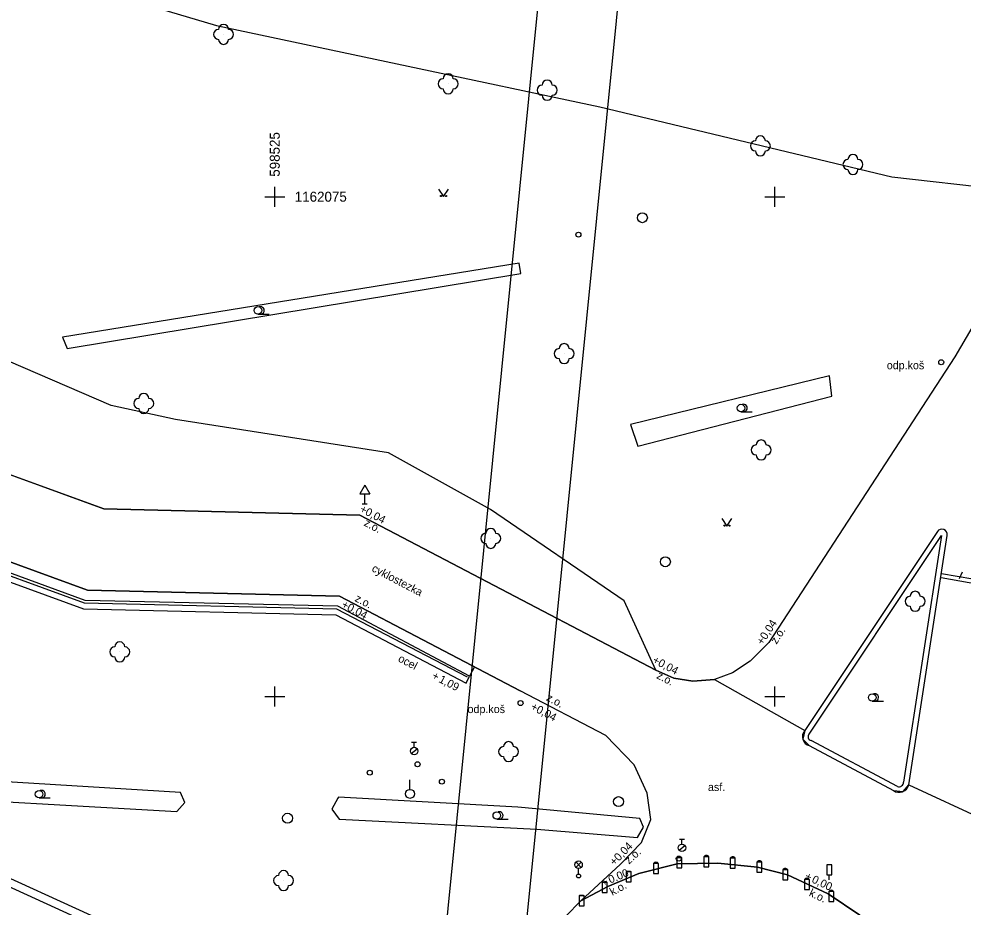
# Model space of a CAD drawing. Extents: x -598693 to -598360, y -1162453 to -1162007.
# Drawn here: x -598537.79 to -598490.58, y -1162110.54 to -1162066.1 of the extents above; entities that cross this region are included whole.
import ezdxf

# ---------------------------------------------------------------- set-up
doc = ezdxf.new("R2010")
doc.units = 0
for name, color, linetype in [('Vrstva 11', 7, 'Continuous'), ('Vrstva 14', 7, 'Continuous'), ('Vrstva 15', 7, 'Continuous'), ('Vrstva 17', 7, 'Continuous'), ('Vrstva 19', 7, 'Continuous'), ('Vrstva 2', 7, 'Continuous'), ('Vrstva 22', 7, 'Continuous'), ('Vrstva 24', 7, 'Continuous'), ('Vrstva 25', 7, 'Continuous'), ('Vrstva 29', 7, 'Continuous'), ('Vrstva 4', 7, 'Continuous'), ('Vrstva 41', 7, 'Continuous'), ('Vrstva 44', 7, 'Continuous'), ('Vrstva 49', 7, 'Continuous'), ('Vrstva 50', 7, 'Continuous'), ('Vrstva 62', 7, 'Continuous'), ('Vrstva 63', 7, 'Continuous'), ('Vrstva 7', 7, 'Continuous')]:
    doc.layers.add(name, color=color, linetype=linetype)

msp = doc.modelspace()

# ---------------------------------------------------------------- linework, layer by layer
at = {"layer": 'Vrstva 11'}
for points in [[(-598535.61, -1162082.02), (-598535.38, -1162082.6), (-598512.7, -1162078.84), (-598512.78, -1162078.32)], [(-598512.78, -1162078.32), (-598535.61, -1162082.02)], [(-598497.14, -1162084.97), (-598497.27, -1162083.96), (-598507.22, -1162086.4), (-598506.85, -1162087.48)], [(-598506.85, -1162087.48), (-598497.14, -1162084.97)], [(-598529.9, -1162105.76), (-598529.5, -1162105.3), (-598529.72, -1162104.81), (-598544.4, -1162103.91), (-598544.73, -1162104.43), (-598544.52, -1162104.92)], [(-598544.52, -1162104.92), (-598529.9, -1162105.76)], [(-598511.89, -1162106.63), (-598506.87, -1162107.06), (-598506.57, -1162106.54), (-598506.75, -1162106.1), (-598512.85, -1162105.53), (-598521.81, -1162105.04), (-598521.84, -1162105.08), (-598522.15, -1162105.64), (-598521.78, -1162106.14)], [(-598521.78, -1162106.14), (-598511.89, -1162106.63)]]:
    msp.add_lwpolyline(points, dxfattribs=at)
at = {"layer": 'Vrstva 14'}
for p, q in [((-598525.84, -1162080.876), (-598525.278, -1162080.876)), ((-598501.689, -1162085.759), (-598501.126, -1162085.759)), ((-598495.126, -1162100.239), (-598494.563, -1162100.239)), ((-598536.784, -1162105.076), (-598536.222, -1162105.076)), ((-598513.899, -1162106.142), (-598513.337, -1162106.142))]:
    msp.add_line(p, q, dxfattribs=at)
for points in [[(-598516.812, -1162074.615), (-598516.562, -1162074.99), (-598516.312, -1162074.615)], [(-598502.64, -1162091.105), (-598502.39, -1162091.48), (-598502.14, -1162091.105)]]:
    msp.add_lwpolyline(points, dxfattribs=at)
for centre, radius in [((-598527.56, -1162066.88), 0.00025), ((-598516.33, -1162069.35), 0.00025), ((-598511.38, -1162069.67), 0.00025), ((-598500.72, -1162072.46), 0.00025), ((-598496.09, -1162073.39), 0.00025), ((-598516.687, -1162074.965), 0.025), ((-598516.437, -1162074.965), 0.025), ((-598525.84, -1162080.688), 0.188), ((-598510.53, -1162082.85), 0.00025), ((-598531.55, -1162085.34), 0.00025), ((-598501.689, -1162085.571), 0.188), ((-598500.68, -1162087.67), 0.00025), ((-598502.515, -1162091.455), 0.025), ((-598502.265, -1162091.455), 0.025), ((-598514.2, -1162092.09), 0.00025), ((-598492.98, -1162095.24), 0.00025), ((-598532.75, -1162097.77), 0.00025), ((-598495.126, -1162100.051), 0.188), ((-598513.31, -1162102.76), 0.00025), ((-598536.784, -1162104.888), 0.188), ((-598513.899, -1162105.954), 0.188), ((-598524.56, -1162109.21), 0.00025)]:
    msp.add_circle(centre, radius, dxfattribs=at)
for centre, radius, start, end in [((-598527.56, -1162066.63), 0.25, 0, 180), ((-598527.81, -1162066.88), 0.25, 90, 270), ((-598527.31, -1162066.88), 0.25, 270, 90), ((-598527.56, -1162067.13), 0.25, 180, 360), ((-598516.33, -1162069.1), 0.25, 0, 180), ((-598516.58, -1162069.35), 0.25, 90, 270), ((-598516.08, -1162069.35), 0.25, 270, 90), ((-598511.38, -1162069.42), 0.25, 0, 180), ((-598516.33, -1162069.6), 0.25, 180, 360), ((-598511.63, -1162069.67), 0.25, 90, 270), ((-598511.13, -1162069.67), 0.25, 270, 90), ((-598511.38, -1162069.92), 0.25, 180, 360), ((-598500.97, -1162072.46), 0.25, 90, 270), ((-598500.72, -1162072.21), 0.25, 0, 180), ((-598500.47, -1162072.46), 0.25, 270, 90), ((-598500.72, -1162072.71), 0.25, 180, 360), ((-598496.34, -1162073.39), 0.25, 90, 270), ((-598496.09, -1162073.14), 0.25, 0, 180), ((-598495.84, -1162073.39), 0.25, 270, 90), ((-598496.09, -1162073.64), 0.25, 180, 360), ((-598525.715, -1162080.688), 0.188, 249.4944, 109.0474), ((-598510.53, -1162082.6), 0.25, 0, 180), ((-598510.78, -1162082.85), 0.25, 90, 270), ((-598510.28, -1162082.85), 0.25, 270, 90), ((-598510.53, -1162083.1), 0.25, 180, 360), ((-598531.55, -1162085.09), 0.25, 0, 180), ((-598531.8, -1162085.34), 0.25, 90, 270), ((-598531.3, -1162085.34), 0.25, 270, 90), ((-598501.564, -1162085.571), 0.188, 249.4944, 109.0474), ((-598531.55, -1162085.59), 0.25, 180, 360), ((-598500.68, -1162087.42), 0.25, 0, 180), ((-598500.93, -1162087.67), 0.25, 90, 270), ((-598500.43, -1162087.67), 0.25, 270, 90), ((-598500.68, -1162087.92), 0.25, 180, 360), ((-598514.45, -1162092.09), 0.25, 90, 270), ((-598514.2, -1162091.84), 0.25, 0, 180), ((-598513.95, -1162092.09), 0.25, 270, 90), ((-598514.2, -1162092.34), 0.25, 180, 360), ((-598492.98, -1162094.99), 0.25, 0, 180), ((-598493.23, -1162095.24), 0.25, 90, 270), ((-598492.73, -1162095.24), 0.25, 270, 90), ((-598492.98, -1162095.49), 0.25, 180, 360), ((-598533, -1162097.77), 0.25, 90, 270), ((-598532.75, -1162097.52), 0.25, 0, 180), ((-598532.5, -1162097.77), 0.25, 270, 90), ((-598532.75, -1162098.02), 0.25, 180, 360), ((-598495.001, -1162100.051), 0.188, 249.4944, 109.0474), ((-598513.31, -1162102.51), 0.25, 0, 180), ((-598513.56, -1162102.76), 0.25, 90, 270), ((-598513.06, -1162102.76), 0.25, 270, 90), ((-598513.31, -1162103.01), 0.25, 180, 360), ((-598536.659, -1162104.888), 0.188, 249.4944, 109.0474), ((-598513.774, -1162105.954), 0.188, 249.4944, 109.0474), ((-598524.81, -1162109.21), 0.25, 90, 270), ((-598524.56, -1162108.96), 0.25, 0, 180), ((-598524.31, -1162109.21), 0.25, 270, 90), ((-598524.56, -1162109.46), 0.25, 180, 360)]:
    msp.add_arc(centre, radius, start, end, dxfattribs=at)
at = {"layer": 'Vrstva 15'}
msp.add_line((-598497.28, -1162109.17), (-598497.28, -1162108.92), dxfattribs=at)
msp.add_lwpolyline([(-598497.405, -1162108.92), (-598497.155, -1162108.92), (-598497.155, -1162108.42), (-598497.405, -1162108.42)], close=True, dxfattribs=at)
for centre, radius in [((-598491.68, -1162083.28), 0.125), ((-598491.68, -1162083.28), 0.00025), ((-598512.71, -1162100.33), 0.125), ((-598512.71, -1162100.33), 0.00025)]:
    msp.add_circle(centre, radius, dxfattribs=at)
at = {"layer": 'Vrstva 17'}
for p, q in [((-598491.87, -1162091.75), (-598498.5, -1162101.71)), ((-598498.28, -1162101.885), (-598491.664, -1162091.946))]:
    msp.add_line(p, q, dxfattribs=at)
for points in [[(-598562.469, -1162084.303), (-598562.81, -1162085.24), (-598547.62, -1162090.84), (-598534.57, -1162095.61), (-598521.94, -1162095.91), (-598515.43, -1162099.34), (-598515.26, -1162098.99)], [(-598521.85, -1162095.48), (-598534.48, -1162095.2), (-598562.21, -1162085.02), (-598562.04, -1162084.57), (-598562.01, -1162084.47)], [(-598491.664, -1162091.946), (-598493.563, -1162104.286)], [(-598493.3, -1162104.42), (-598491.38, -1162091.94)], [(-598515.26, -1162098.99), (-598521.85, -1162095.48)], [(-598493.865, -1162104.502), (-598498.182, -1162102.195)], [(-598498.28, -1162102.46), (-598494.07, -1162104.71)]]:
    msp.add_lwpolyline(points, dxfattribs=at)
for centre, radius, start, end in [((-598491.648, -1162091.903), 0.27, 352.1581, 145.4538), ((-598498.157, -1162102.017), 0.46, 138.2563, 254.4401), ((-598498.157, -1162102.017), 0.18, 133.4026, 262.0107), ((-598493.789, -1162104.289), 0.226, 250.2488, 0.6288), ((-598493.789, -1162104.289), 0.506, 236.2848, 344.9903)]:
    msp.add_arc(centre, radius, start, end, dxfattribs=at)
at = {"layer": 'Vrstva 19'}
for p, q in [((-598520.5, -1162089.437), (-598520.75, -1162089.87)), ((-598520.5, -1162089.437), (-598520.25, -1162089.87)), ((-598520.75, -1162089.87), (-598520.25, -1162089.87)), ((-598520.5, -1162090.37), (-598520.5, -1162089.87)), ((-598520.625, -1162090.37), (-598520.375, -1162090.37))]:
    msp.add_line(p, q, dxfattribs=at)
at = {"layer": 'Vrstva 2'}
for points in [[(-598692.873, -1162424.561), (-598651.24, -1162006.63), (-598503.471, -1162021.35), (-598545.104, -1162439.282)], [(-598692.873, -1162424.561), (-598651.24, -1162006.63), (-598503.471, -1162021.35), (-598545.104, -1162439.282)], [(-598507.399, -1162020.712), (-598549.031, -1162438.644), (-598401.263, -1162453.364), (-598359.63, -1162035.432)]]:
    msp.add_lwpolyline(points, close=True, dxfattribs=at)
at = {"layer": 'Vrstva 22'}
msp.add_lwpolyline([(-598515.36, -1162099.04), (-598521.9, -1162095.63), (-598534.52, -1162095.33), (-598547.5, -1162090.6), (-598562.42, -1162085.09), (-598557.86, -1162072.77)], dxfattribs=at)
at = {"layer": 'Vrstva 24'}
for p, q in [((-598518.155, -1162102.292), (-598517.905, -1162102.292)), ((-598518.03, -1162102.542), (-598518.03, -1162102.292)), ((-598518.177, -1162102.846), (-598517.882, -1162102.614)), ((-598504.765, -1162107.132), (-598504.515, -1162107.132)), ((-598504.64, -1162107.382), (-598504.64, -1162107.132)), ((-598504.787, -1162107.686), (-598504.492, -1162107.454))]:
    msp.add_line(p, q, dxfattribs=at)
for centre, radius in [((-598509.82, -1162076.9), 0.125), ((-598518.03, -1162102.73), 0.188), ((-598517.86, -1162103.39), 0.125), ((-598520.25, -1162103.81), 0.125), ((-598516.64, -1162104.26), 0.125), ((-598504.64, -1162107.57), 0.188), ((-598504.8, -1162108.11), 0.125)]:
    msp.add_circle(centre, radius, dxfattribs=at)
at = {"layer": 'Vrstva 25'}
for points in [[(-598491.66, -1162093.84), (-598487.75, -1162094.52)], [(-598491.68, -1162094.05), (-598487.77, -1162094.75)]]:
    msp.add_lwpolyline(points, dxfattribs=at)
for centre in [(-598506.62, -1162076.05), (-598505.47, -1162093.26), (-598507.81, -1162105.26), (-598524.36, -1162106.09)]:
    msp.add_circle(centre, 0.25, dxfattribs=at)
at = {"layer": 'Vrstva 29'}
for p, q in [((-598509.942, -1162108.549), (-598509.678, -1162108.285)), ((-598509.674, -1162108.548), (-598509.938, -1162108.283)), ((-598509.81, -1162108.88), (-598509.81, -1162108.605))]:
    msp.add_line(p, q, dxfattribs=at)
for centre, radius in [((-598509.81, -1162108.417), 0.188), ((-598509.81, -1162108.98), 0.1)]:
    msp.add_circle(centre, radius, dxfattribs=at)
at = {"layer": 'Vrstva 4'}
msp.add_lwpolyline([(-598549.81, -1162104.23), (-598524.16, -1162115.97)], dxfattribs=at)
at = {"layer": 'Vrstva 41'}
for points in [[(-598555.19, -1162057.68), (-598541.03, -1162062.54), (-598527.91, -1162066.44), (-598508.75, -1162070.51), (-598494.14, -1162074), (-598488.83, -1162074.61)], [(-598505.95, -1162098.69), (-598507.53, -1162095.22), (-598514.22, -1162090.64), (-598519.32, -1162087.82), (-598529.96, -1162086.14), (-598533.18, -1162085.44), (-598556.77, -1162075.25)]]:
    msp.add_lwpolyline(points, dxfattribs=at)
at = {"layer": 'Vrstva 44'}
msp.add_line((-598518.24, -1162104.645), (-598518.24, -1162104.174), dxfattribs=at)
for points in [[(-598504.905, -1162108.57), (-598504.655, -1162108.57), (-598504.655, -1162108.07), (-598504.905, -1162108.07)], [(-598503.545, -1162108.52), (-598503.295, -1162108.52), (-598503.295, -1162108.02), (-598503.545, -1162108.02)], [(-598502.225, -1162108.58), (-598501.975, -1162108.58), (-598501.975, -1162108.08), (-598502.225, -1162108.08)], [(-598506.065, -1162108.86), (-598505.815, -1162108.86), (-598505.815, -1162108.36), (-598506.065, -1162108.36)], [(-598500.895, -1162108.79), (-598500.645, -1162108.79), (-598500.645, -1162108.29), (-598500.895, -1162108.29)], [(-598507.435, -1162109.27), (-598507.185, -1162109.27), (-598507.185, -1162108.77), (-598507.435, -1162108.77)], [(-598499.605, -1162109.17), (-598499.355, -1162109.17), (-598499.355, -1162108.67), (-598499.605, -1162108.67)], [(-598508.635, -1162109.81), (-598508.385, -1162109.81), (-598508.385, -1162109.31), (-598508.635, -1162109.31)], [(-598498.515, -1162109.66), (-598498.265, -1162109.66), (-598498.265, -1162109.16), (-598498.515, -1162109.16)], [(-598509.785, -1162110.48), (-598509.535, -1162110.48), (-598509.535, -1162109.98), (-598509.785, -1162109.98)], [(-598497.305, -1162110.26), (-598497.055, -1162110.26), (-598497.055, -1162109.76), (-598497.305, -1162109.76)]]:
    msp.add_lwpolyline(points, close=True, dxfattribs=at)
for points in [[(-598507.435, -1162108.77), (-598507.396, -1162108.731), (-598507.224, -1162108.731), (-598507.185, -1162108.77)], [(-598508.635, -1162109.31), (-598508.596, -1162109.271), (-598508.424, -1162109.271), (-598508.385, -1162109.31)], [(-598509.785, -1162109.98), (-598509.746, -1162109.941), (-598509.574, -1162109.941), (-598509.535, -1162109.98)]]:
    msp.add_lwpolyline(points, dxfattribs=at)
msp.add_circle((-598518.24, -1162104.87), 0.225, dxfattribs=at)
for centre in [(-598504.78, -1162108.155), (-598503.42, -1162108.105), (-598502.1, -1162108.165), (-598505.94, -1162108.445), (-598500.77, -1162108.375), (-598499.48, -1162108.755), (-598498.39, -1162109.245), (-598497.18, -1162109.845)]:
    msp.add_arc(centre, 0.151, 34.3319, 145.6681, dxfattribs=at)
at = {"layer": 'Vrstva 49'}
msp.add_line((-598490.76, -1162094.09), (-598490.61, -1162093.76), dxfattribs=at)
at = {"layer": 'Vrstva 62'}
for p, q in [((-598525, -1162075.5), (-598525, -1162074.5)), ((-598500, -1162075.5), (-598500, -1162074.5)), ((-598525.5, -1162075), (-598524.5, -1162075)), ((-598500.5, -1162075), (-598499.5, -1162075)), ((-598525, -1162100.5), (-598525, -1162099.5)), ((-598500, -1162100.5), (-598500, -1162099.5)), ((-598525.5, -1162100), (-598524.5, -1162100)), ((-598500.5, -1162100), (-598499.5, -1162100))]:
    msp.add_line(p, q, dxfattribs=at)
at = {"layer": 'Vrstva 63'}
for points in [[(-598592.55, -1162069.05), (-598560.62, -1162080.68), (-598560.479, -1162080.296), (-598559.04, -1162080.81), (-598540.93, -1162087.41), (-598541.096, -1162087.866), (-598533.54, -1162090.62), (-598520.75, -1162090.93), (-598515.43, -1162093.72), (-598505.95, -1162098.69), (-598505.05, -1162099.08), (-598504.09, -1162099.24), (-598503.02, -1162099.15), (-598498.5, -1162101.71), (-598498.6, -1162102.14), (-598498.28, -1162102.46), (-598494.07, -1162104.71), (-598493.58, -1162104.75), (-598493.3, -1162104.42), (-598489.48, -1162106.19)], [(-598495.75, -1162110.94), (-598497.33, -1162109.88), (-598499.36, -1162108.93), (-598500.86, -1162108.54), (-598502.84, -1162108.33), (-598504.88, -1162108.37), (-598506.79, -1162108.86), (-598508.35, -1162109.5), (-598509.69, -1162110.22), (-598507.71, -1162108.38), (-598506.66, -1162107.3), (-598506.19, -1162106.16), (-598506.38, -1162104.83), (-598507.03, -1162103.42), (-598508.44, -1162101.96), (-598512.73, -1162099.71), (-598521.77, -1162094.99), (-598534.36, -1162094.69), (-598561.74, -1162084.67)]]:
    msp.add_lwpolyline(points, dxfattribs=at)
at = {"layer": 'Vrstva 7'}
msp.add_line((-598515.013, -1162098.518), (-598515.26, -1162098.99), dxfattribs=at)
for points in [[(-598488.761, -1162078.591), (-598489.47, -1162080.39), (-598491, -1162083.01), (-598500.3, -1162097.3), (-598501.23, -1162098.24), (-598502.11, -1162098.81), (-598503.02, -1162099.15), (-598504.09, -1162099.24), (-598505.05, -1162099.08), (-598505.95, -1162098.69)], [(-598505.95, -1162098.69), (-598515.43, -1162093.72), (-598520.75, -1162090.93), (-598533.54, -1162090.62), (-598559.23, -1162081.28)], [(-598562.04, -1162084.57), (-598561.82, -1162084.63), (-598561.74, -1162084.67), (-598534.36, -1162094.69), (-598521.77, -1162094.99), (-598512.73, -1162099.71)], [(-598508.44, -1162101.96), (-598512.73, -1162099.71)], [(-598509.69, -1162110.22), (-598507.71, -1162108.38), (-598506.66, -1162107.3), (-598506.19, -1162106.16), (-598506.38, -1162104.83), (-598507.03, -1162103.42), (-598508.44, -1162101.96)], [(-598549.97, -1162103.74), (-598523.61, -1162115.77)], [(-598530.873, -1162130.589), (-598523.34, -1162134.66), (-598514.55, -1162116.09), (-598513.68, -1162114.72), (-598512.67, -1162113.31), (-598511.43, -1162111.95), (-598510.44, -1162110.99), (-598509.69, -1162110.22), (-598508.35, -1162109.5), (-598506.79, -1162108.86), (-598504.88, -1162108.37), (-598502.84, -1162108.33), (-598500.86, -1162108.54), (-598499.36, -1162108.93), (-598497.33, -1162109.88), (-598495.75, -1162110.94), (-598494.29, -1162112.25), (-598493.3, -1162113.32), (-598492.51, -1162114.63), (-598491.87, -1162116.09), (-598491.45, -1162117.58), (-598491.39, -1162119.13)]]:
    msp.add_lwpolyline(points, dxfattribs=at)

# ---------------------------------------------------------------- texts
at = {"layer": 'Vrstva 49'}
for s, p in [('odp.koš', (-598494.4, -1162083.63)), ('odp.koš', (-598515.36, -1162100.83)), ('asf.', (-598503.34, -1162104.73))]:
    msp.add_text(s, height=0.4, dxfattribs=at).set_placement(p)
for s, rotation, p in [('z.o.', 332.3259, (-598520.575, -1162091.436)), ('cyklostezka', 332.3385, (-598520.185, -1162093.713)), ('z.o.', 332.4299, (-598521.03, -1162095.214)), ('z.o.', 56.9437, (-598499.913, -1162097.41)), ('ocel', 332.4622, (-598518.869, -1162098.227)), ('z.o.', 332.3337, (-598505.943, -1162099.072)), ('z.o.', 332.4299, (-598511.46, -1162100.18)), ('z.o.', 42.9011, (-598507.285, -1162108.411)), ('k.o.', 28.2497, (-598508.12, -1162109.976)), ('k.o.', 334.9213, (-598498.32, -1162109.959))]:
    msp.add_text(s, height=0.4, rotation=rotation, dxfattribs=at).set_placement(p)
at = {"layer": 'Vrstva 50'}
for s, rotation, p in [('+0,04', 332.3259, (-598520.791, -1162090.746)), ('+0,04', 332.4299, (-598521.698, -1162095.525)), ('+0,04', 56.9437, (-598500.608, -1162097.455)), ('+0,04', 332.3337, (-598506.151, -1162098.301)), ('+', 332.4622, (-598517.182, -1162099.083)), ('1,09', 332.4622, (-598516.833, -1162099.265)), ('+0,04', 332.3241, (-598512.241, -1162100.63)), ('+0,04', 45.8069, (-598508.015, -1162108.492)), ('0,00', 22.3062, (-598508.226, -1162109.363)), ('+', 334.9213, (-598498.54, -1162109.121)), ('0,00', 334.9213, (-598498.184, -1162109.288)), ('+', 22.3062, (-598508.59, -1162109.513))]:
    msp.add_text(s, height=0.4, rotation=rotation, dxfattribs=at).set_placement(p)
at = {"layer": 'Vrstva 62'}
msp.add_text('598525', height=0.5, rotation=90, dxfattribs=at).set_placement((-598524.75, -1162074))
msp.add_text('1162075', height=0.5, dxfattribs=at).set_placement((-598524, -1162075.25))

doc.saveas('drawing.dxf')
